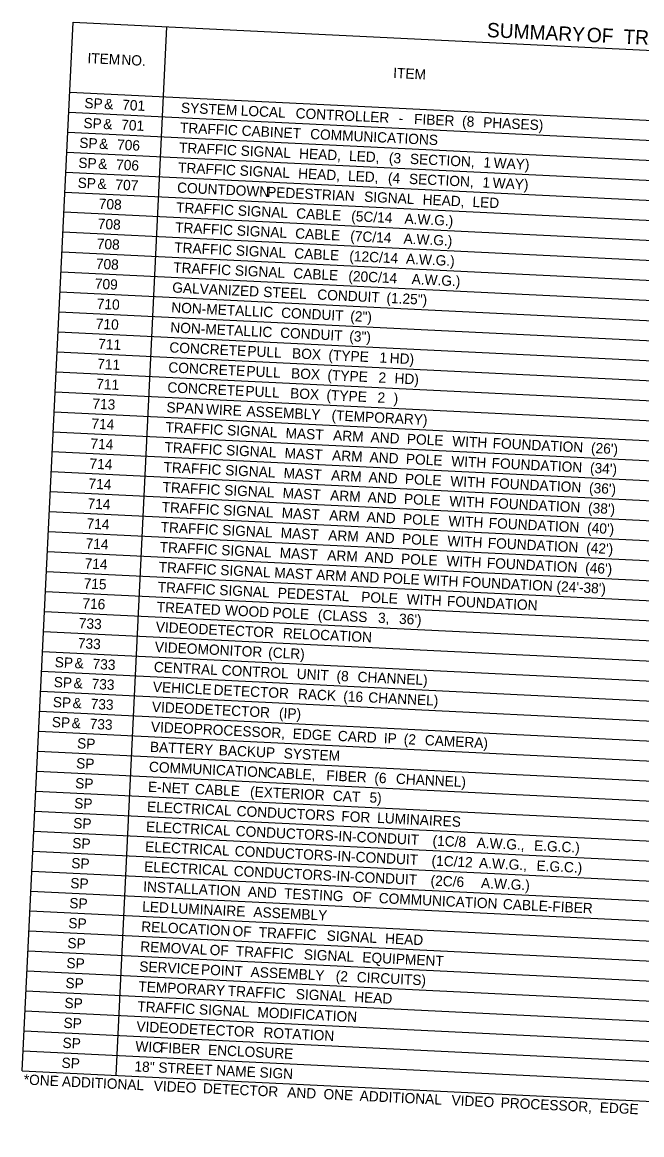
# Model space of a CAD drawing. Extents: x 669100 to 670534, y 743337 to 744379.
# Drawn here: x 670213.3 to 670358.8, y 743747.4 to 744008.6 of the extents above; entities that cross this region are included whole.
import ezdxf

# ---------------------------------------------------------------- set-up
doc = ezdxf.new("R2010")
doc.units = 0
doc.layers.add('R_Dimension', color=7, linetype='Continuous')

msp = doc.modelspace()

# ---------------------------------------------------------------- linework, layer by layer
at = {"layer": 'R_Dimension'}
for p, q in [((670213.29, 743762.42), (670225.24, 744008.56)), ((670225.24, 744008.56), (670534.49, 743993.54)), ((670235.33, 743761.35), (670247.28, 744007.49)), ((670224.45, 743992.15), (670533.69, 743977.13)), ((670224.22, 743987.46), (670533.46, 743972.45)), ((670223.99, 743982.77), (670533.23, 743967.76)), ((670223.76, 743978.09), (670533.01, 743963.07)), ((670223.54, 743973.4), (670532.78, 743958.38)), ((670223.31, 743968.71), (670532.55, 743953.69)), ((670223.08, 743964.02), (670532.32, 743949)), ((670222.85, 743959.33), (670532.09, 743944.32)), ((670222.63, 743954.64), (670531.87, 743939.63)), ((670222.4, 743949.96), (670531.64, 743934.94)), ((670222.17, 743945.27), (670531.41, 743930.25)), ((670221.94, 743940.58), (670531.18, 743925.56)), ((670221.71, 743935.89), (670530.96, 743920.87)), ((670221.49, 743931.2), (670530.73, 743916.19)), ((670221.26, 743926.51), (670530.5, 743911.5)), ((670221.03, 743921.83), (670530.27, 743906.81)), ((670220.8, 743917.14), (670530.05, 743902.12)), ((670220.58, 743912.45), (670529.82, 743897.43)), ((670220.35, 743907.76), (670529.59, 743892.74)), ((670220.12, 743903.07), (670529.36, 743888.05)), ((670219.89, 743898.38), (670529.14, 743883.37)), ((670219.67, 743893.69), (670528.91, 743878.68)), ((670219.44, 743889.01), (670528.68, 743873.99)), ((670219.21, 743884.32), (670528.45, 743869.3)), ((670218.98, 743879.63), (670528.22, 743864.61)), ((670218.76, 743874.94), (670528, 743859.92)), ((670218.53, 743870.25), (670527.77, 743855.24)), ((670218.3, 743865.56), (670527.54, 743850.55)), ((670218.07, 743860.88), (670527.31, 743845.86)), ((670217.84, 743856.19), (670527.09, 743841.17)), ((670217.62, 743851.5), (670526.86, 743836.48)), ((670217.39, 743846.81), (670526.63, 743831.79)), ((670217.16, 743842.12), (670526.4, 743827.11)), ((670216.93, 743837.43), (670526.18, 743822.42)), ((670216.71, 743832.75), (670525.95, 743817.73)), ((670216.48, 743828.06), (670525.72, 743813.04)), ((670216.25, 743823.37), (670525.49, 743808.35)), ((670216.02, 743818.68), (670525.26, 743803.66)), ((670215.8, 743813.99), (670525.04, 743798.98)), ((670215.57, 743809.3), (670524.81, 743794.29)), ((670215.34, 743804.62), (670524.58, 743789.6)), ((670215.11, 743799.93), (670524.35, 743784.91)), ((670214.88, 743795.24), (670524.13, 743780.22)), ((670214.66, 743790.55), (670523.9, 743775.53)), ((670214.43, 743785.86), (670523.67, 743770.85)), ((670214.2, 743781.17), (670523.44, 743766.16)), ((670213.97, 743776.49), (670523.22, 743761.47)), ((670213.75, 743771.8), (670522.99, 743756.78)), ((670213.52, 743767.11), (670522.76, 743752.09)), ((670213.29, 743762.42), (670522.53, 743747.4))]:
    msp.add_line(p, q, dxfattribs=at)

# ---------------------------------------------------------------- texts
for s, height, p in [('SUMMARY', 3.37, (670322.35, 744005.09)), (' OF', 3.37, (670344.56, 744004.02)), (' TRAFFIC', 3.37, (670353.15, 744003.6)), ('ITEM', 2.407, (670228.56, 743998.97)), (' NO.', 2.407, (670235.64, 743998.63)), ('ITEM', 2.407, (670300.36, 743995.48)), ('SP', 2.407, (670227.84, 743988.43)), (' &', 2.407, (670231.61, 743988.25)), (' 701', 2.407, (670235.83, 743988.04)), ('SYSTEM', 2.407, (670250.53, 743987.33)), (' LOCAL', 2.407, (670263.67, 743986.69)), (' CONTROLLER', 2.4071, (670276.56, 743986.07)), ('SP', 2.407, (670227.62, 743983.74)), (' &', 2.407, (670231.38, 743983.56)), (' 701', 2.407, (670235.6, 743983.35)), (' -', 2.407, (670300.79, 743984.89)), (' FIBER', 2.407, (670304.37, 743984.71)), (' (8', 2.407, (670315.65, 743984.17)), (' PHASES)', 2.407, (670320.6, 743983.93)), ('TRAFFIC', 2.407, (670250.3, 743982.64)), (' CABINET', 2.407, (670263.88, 743981.98)), (' COMMUNICATIONS', 2.4071, (670279.97, 743981.2)), ('SP', 2.407, (670226.64, 743979.09)), (' &', 2.407, (670230.41, 743978.91)), (' 706', 2.407, (670234.63, 743978.7)), ('TRAFFIC', 2.407, (670250.07, 743977.95)), (' SIGNAL', 2.407, (670263.65, 743977.29)), (' HEAD,', 2.407, (670277.37, 743976.63)), (' LED,', 2.407, (670289.09, 743976.06)), (' (3', 2.407, (670298.46, 743975.6)), (' SECTION,', 2.407, (670303.4, 743975.36)), ('SP', 2.407, (670226.41, 743974.4)), (' &', 2.407, (670230.18, 743974.22)), (' 706', 2.407, (670234.4, 743974.01)), ('TRAFFIC', 2.407, (670249.85, 743973.26)), (' SIGNAL', 2.407, (670263.42, 743972.61)), (' 1', 2.407, (670320.65, 743974.53)), (' WAY)', 2.407, (670323.06, 743974.41)), (' HEAD,', 2.407, (670277.15, 743971.94)), (' LED,', 2.407, (670288.86, 743971.37)), (' (4', 2.407, (670298.24, 743970.91)), (' SECTION,', 2.407, (670303.18, 743970.67)), ('SP', 2.407, (670226.25, 743969.71)), (' &', 2.407, (670230.02, 743969.53)), (' 707', 2.407, (670234.24, 743969.32)), ('COUNTDOWN', 2.407, (670249.62, 743968.58)), (' PEDESTRIAN', 2.4071, (670269.86, 743967.59)), (' 1', 2.407, (670320.42, 743969.84)), (' WAY)', 2.407, (670322.83, 743969.72)), ('708', 2.407, (670231.22, 743964.77)), (' SIGNAL', 2.407, (670292.65, 743966.49)), (' HEAD,', 2.407, (670306.38, 743965.82)), (' LED', 2.407, (670318.09, 743965.25)), ('TRAFFIC', 2.407, (670249.39, 743963.89)), (' SIGNAL', 2.407, (670262.97, 743963.23)), (' CABLE', 2.407, (670276.69, 743962.56)), ('708', 2.407, (670230.99, 743960.08)), (' (5C/14', 2.407, (670289.62, 743961.93)), (' A.W.G.)', 2.407, (670302.13, 743961.33)), ('TRAFFIC', 2.407, (670249.16, 743959.2)), (' SIGNAL', 2.407, (670262.74, 743958.54)), (' CABLE', 2.407, (670276.46, 743957.87)), (' (7C/14', 2.407, (670289.39, 743957.25)), ('708', 2.407, (670230.76, 743955.39)), ('TRAFFIC', 2.407, (670248.94, 743954.51)), (' A.W.G.)', 2.407, (670301.91, 743956.64)), (' SIGNAL', 2.407, (670262.51, 743953.85)), (' CABLE', 2.407, (670276.24, 743953.19)), (' (12C/14', 2.407, (670289.17, 743952.56)), (' A.W.G.)', 2.407, (670302.47, 743951.91)), ('708', 2.407, (670230.54, 743950.7)), ('TRAFFIC', 2.407, (670248.71, 743949.82)), (' SIGNAL', 2.407, (670262.28, 743949.16)), (' CABLE', 2.407, (670276.01, 743948.5)), (' (20C/14', 2.407, (670288.94, 743947.87)), (' A.W.G.)', 2.407, (670303.8, 743947.15)), ('709', 2.407, (670230.3, 743946.02)), ('GALVANIZED', 2.407, (670248.48, 743945.13)), (' STEEL', 2.407, (670268.95, 743944.14)), ('710', 2.407, (670230.75, 743941.3)), (' CONDUIT', 2.407, (670281.65, 743943.52)), (' (1.25")', 2.407, (670297.89, 743942.73)), ('NON-METALLIC', 2.4071, (670248.25, 743940.45)), (' CONDUIT', 2.407, (670273.15, 743939.24)), (' (2")', 2.407, (670289.39, 743938.45)), ('710', 2.407, (670230.53, 743936.61)), ('NON-METALLIC', 2.4071, (670248.03, 743935.76)), (' CONDUIT', 2.407, (670272.92, 743934.55)), (' (3")', 2.407, (670289.16, 743933.76)), ('711', 2.407, (670231.08, 743931.88)), ('CONCRETE', 2.407, (670247.8, 743931.07)), (' PULL', 2.407, (670265.21, 743930.22)), (' BOX', 2.407, (670275.72, 743929.71)), (' (TYPE', 2.407, (670284.26, 743929.3)), (' 1', 2.407, (670296.24, 743928.72)), (' HD)', 2.407, (670298.65, 743928.6)), ('711', 2.407, (670230.86, 743927.19)), ('CONCRETE', 2.407, (670247.57, 743926.38)), (' PULL', 2.407, (670264.99, 743925.53)), (' BOX', 2.407, (670275.49, 743925.02)), (' (TYPE', 2.407, (670284.03, 743924.61)), (' 2', 2.407, (670296.02, 743924.03)), (' HD)', 2.407, (670299.78, 743923.85)), ('711', 2.407, (670230.63, 743922.5)), ('CONCRETE', 2.407, (670247.34, 743921.69)), (' PULL', 2.407, (670264.76, 743920.85)), (' BOX', 2.407, (670275.27, 743920.34)), ('713', 2.407, (670229.72, 743917.85)), (' (TYPE', 2.407, (670283.8, 743919.92)), (' 2', 2.407, (670295.79, 743919.34)), (' )', 2.407, (670299.56, 743919.16)), ('SPAN', 2.407, (670247.11, 743917)), (' WIRE', 2.407, (670255.5, 743916.6)), (' ASSEMBLY', 2.407, (670265.02, 743916.13)), (' (TEMPORARY)', 2.4071, (670285, 743915.16)), ('714', 2.407, (670229.49, 743913.16)), ('TRAFFIC', 2.407, (670246.89, 743912.32)), (' SIGNAL', 2.407, (670260.46, 743911.66)), (' MAST', 2.407, (670274.19, 743910.99)), (' ARM', 2.407, (670285.36, 743910.45)), (' AND', 2.407, (670294.16, 743910.02)), ('714', 2.407, (670229.26, 743908.47)), ('TRAFFIC', 2.407, (670246.66, 743907.63)), (' POLE', 2.407, (670302.68, 743909.61)), (' WITH', 2.407, (670313.34, 743909.09)), (' FOUNDATION', 2.4071, (670322.82, 743908.63)), (" (26')", 2.407, (670345.92, 743907.51)), (' SIGNAL', 2.407, (670260.23, 743906.97)), (' MAST', 2.407, (670273.96, 743906.3)), (' ARM', 2.407, (670285.13, 743905.76)), (' AND', 2.407, (670293.93, 743905.33)), (' POLE', 2.407, (670302.45, 743904.92)), ('714', 2.407, (670229.04, 743903.78)), ('TRAFFIC', 2.407, (670246.43, 743902.94)), (' SIGNAL', 2.407, (670260.01, 743902.28)), (' WITH', 2.407, (670313.11, 743904.4)), (' FOUNDATION', 2.4071, (670322.59, 743903.94)), (" (34')", 2.407, (670345.69, 743902.82)), (' MAST', 2.407, (670273.73, 743901.61)), (' ARM', 2.407, (670284.9, 743901.07)), (' AND', 2.407, (670293.7, 743900.64)), (' POLE', 2.407, (670302.22, 743900.23)), (' WITH', 2.407, (670312.88, 743899.71)), ('714', 2.407, (670228.81, 743899.09)), ('TRAFFIC', 2.407, (670246.2, 743898.25)), (' SIGNAL', 2.407, (670259.78, 743897.59)), (' MAST', 2.407, (670273.5, 743896.92)), (' FOUNDATION', 2.4071, (670322.37, 743899.25)), (" (36')", 2.407, (670345.46, 743898.13)), ('714', 2.407, (670228.58, 743894.41)), (' ARM', 2.407, (670284.67, 743896.38)), (' AND', 2.407, (670293.48, 743895.95)), (' POLE', 2.407, (670302, 743895.54)), (' WITH', 2.407, (670312.65, 743895.02)), (' FOUNDATION', 2.4071, (670322.14, 743894.56)), ('TRAFFIC', 2.407, (670245.98, 743893.56)), (' SIGNAL', 2.407, (670259.55, 743892.9)), (' MAST', 2.407, (670273.28, 743892.24)), (' ARM', 2.407, (670284.45, 743891.69)), (" (38')", 2.407, (670345.23, 743893.44)), ('714', 2.407, (670228.35, 743889.72)), (' AND', 2.407, (670293.25, 743891.27)), (' POLE', 2.407, (670301.77, 743890.85)), (' WITH', 2.407, (670312.43, 743890.34)), (' FOUNDATION', 2.4071, (670321.91, 743889.87)), ('TRAFFIC', 2.407, (670245.75, 743888.87)), (' SIGNAL', 2.407, (670259.32, 743888.21)), (' MAST', 2.407, (670273.05, 743887.55)), (' ARM', 2.407, (670284.22, 743887.01)), (' AND', 2.407, (670293.02, 743886.58)), (" (40')", 2.407, (670345.01, 743888.75)), ('714', 2.407, (670228.13, 743885.03)), ('TRAFFIC', 2.407, (670245.52, 743884.19)), (' POLE', 2.407, (670301.54, 743886.16)), (' WITH', 2.407, (670312.2, 743885.65)), (' FOUNDATION', 2.4071, (670321.68, 743885.19)), (" (42')", 2.407, (670344.78, 743884.06)), (' SIGNAL', 2.407, (670259.09, 743883.53)), (' MAST', 2.407, (670272.82, 743882.86)), (' ARM', 2.407, (670283.99, 743882.32)), (' AND', 2.407, (670292.79, 743881.89)), (' POLE', 2.407, (670301.31, 743881.48)), ('714', 2.407, (670227.9, 743880.34)), ("TRAFFIC SIGNAL MAST ARM AND POLE WITH FOUNDATION (24'-38')", 2.4071, (670245.29, 743879.5)), (' WITH', 2.407, (670311.97, 743880.96)), (' FOUNDATION', 2.4071, (670321.46, 743880.5)), (" (46')", 2.407, (670344.55, 743879.38)), ('715', 2.407, (670227.67, 743875.65)), ('TRAFFIC', 2.407, (670245.07, 743874.81)), (' SIGNAL', 2.407, (670258.64, 743874.15)), (' PEDESTAL', 2.407, (670272.36, 743873.48)), ('716', 2.407, (670227.38, 743870.97)), (' POLE', 2.407, (670291.96, 743872.53)), (' WITH', 2.407, (670302.62, 743872.01)), (' FOUNDATION', 2.4071, (670312.1, 743871.55)), ('TREATED', 2.407, (670244.84, 743870.12)), (' WOOD', 2.407, (670259.96, 743869.39)), (' POLE', 2.407, (670271.13, 743868.84)), (' (CLASS', 2.407, (670281.79, 743868.33)), ('733', 2.407, (670226.53, 743866.31)), ('VIDEO', 2.407, (670244.61, 743865.43)), (' 3,', 2.407, (670295.9, 743867.64)), (" 36')", 2.407, (670300.84, 743867.4)), (' DETECTOR', 2.407, (670253.75, 743864.99)), (' RELOCATION', 2.4071, (670273.56, 743864.03)), ('733', 2.407, (670226.31, 743861.62)), ('VIDEO', 2.407, (670244.38, 743860.74)), (' MONITOR', 2.407, (670253.53, 743860.3)), (' (CLR)', 2.407, (670270.11, 743859.49)), ('SP', 2.407, (670220.88, 743857.18)), (' &', 2.407, (670224.65, 743857)), (' 733', 2.407, (670228.87, 743856.8)), ('CENTRAL', 2.407, (670244.16, 743856.05)), (' CONTROL', 2.407, (670259.19, 743855.32)), ('SP', 2.407, (670220.65, 743852.5)), (' UNIT', 2.407, (670276.81, 743854.47)), (' (8', 2.407, (670286.16, 743854.01)), (' CHANNEL)', 2.407, (670291.11, 743853.77)), (' &', 2.407, (670224.42, 743852.31)), (' 733', 2.407, (670228.64, 743852.11)), ('VEHICLE', 2.407, (670243.93, 743851.37)), (' DETECTOR', 2.407, (670257.29, 743850.72)), (' RACK', 2.407, (670277.1, 743849.76)), ('SP', 2.407, (670220.43, 743847.81)), (' &', 2.407, (670224.19, 743847.63)), (' 733', 2.407, (670228.42, 743847.42)), (' (16', 2.407, (670287.75, 743849.24)), (' CHANNEL)', 2.407, (670293.62, 743848.95)), ('VIDEO', 2.407, (670243.7, 743846.68)), (' DETECTOR', 2.407, (670252.84, 743846.23)), (' (IP)', 2.407, (670272.65, 743845.27)), ('SP', 2.407, (670220.2, 743843.12)), (' &', 2.407, (670223.97, 743842.94)), (' 733', 2.407, (670228.19, 743842.73)), ('VIDEO', 2.407, (670243.47, 743841.99)), (' PROCESSOR,', 2.4071, (670252.62, 743841.55)), (' EDGE', 2.407, (670275.88, 743840.42)), (' CARD', 2.407, (670286.47, 743839.9)), (' IP', 2.407, (670297.26, 743839.38)), ('SP', 2.407, (670226.12, 743838.13)), ('BATTERY', 2.407, (670243.24, 743837.3)), (' (2', 2.407, (670301.95, 743839.15)), (' CAMERA)', 2.407, (670306.89, 743838.91)), (' BACKUP', 2.407, (670258.5, 743836.56)), (' SYSTEM', 2.407, (670273.76, 743835.82)), ('SP', 2.407, (670225.9, 743833.44)), ('COMMUNICATION', 2.4071, (670243.02, 743832.61)), (' CABLE,', 2.407, (670269.77, 743831.31)), (' FIBER', 2.407, (670283.76, 743830.63)), (' (6', 2.407, (670295.04, 743830.09)), (' CHANNEL)', 2.407, (670300.11, 743829.84)), ('SP', 2.407, (670225.67, 743828.76)), ('E-NET', 2.407, (670242.79, 743827.92)), (' CABLE', 2.407, (670252.92, 743827.43)), (' (EXTERIOR', 2.407, (670265.85, 743826.8)), ('SP', 2.407, (670225.44, 743824.07)), (' CAT', 2.407, (670285.31, 743825.86)), (' 5)', 2.407, (670293.9, 743825.44)), ('ELECTRICAL', 2.407, (670242.56, 743823.24)), (' CONDUCTORS', 2.4071, (670262.7, 743822.26)), (' FOR', 2.407, (670287.3, 743821.06)), ('SP', 2.407, (670225.21, 743819.38)), ('ELECTRICAL', 2.407, (670242.33, 743818.55)), (' LUMINAIRES', 2.4071, (670295.7, 743820.66)), (' CONDUCTORS-IN-CONDUIT', 2.4071, (670262.48, 743817.57)), ('SP', 2.407, (670224.99, 743814.69)), ('ELECTRICAL', 2.407, (670242.11, 743813.86)), (' (1C/8', 2.407, (670308.71, 743815.32)), (' A.W.G.,', 2.407, (670319.06, 743814.82)), (' E.G.C.)', 2.407, (670332.56, 743814.17)), (' CONDUCTORS-IN-CONDUIT', 2.4071, (670262.25, 743812.88)), (' (1C/12', 2.407, (670308.48, 743810.64)), ('SP', 2.407, (670224.76, 743810)), ('ELECTRICAL', 2.407, (670241.88, 743809.17)), (' CONDUCTORS-IN-CONDUIT', 2.4071, (670262.02, 743808.19)), (' A.W.G.,', 2.407, (670319.63, 743810.09)), (' E.G.C.)', 2.407, (670333.13, 743809.44)), ('SP', 2.407, (670224.53, 743805.31)), (' (2C/6', 2.407, (670308.25, 743805.95)), ('INSTALLATION', 2.4071, (670241.65, 743804.48)), (' AND', 2.407, (670265.33, 743803.33)), (' TESTING', 2.407, (670273.85, 743802.92)), (' A.W.G.)', 2.407, (670320.1, 743805.37)), ('SP', 2.407, (670224.3, 743800.63)), (' OF', 2.407, (670289.94, 743802.14)), (' COMMUNICATION', 2.4071, (670296.08, 743801.84)), (' CABLE-FIBER', 2.4071, (670325.23, 743800.42)), ('LED', 2.407, (670241.42, 743799.79)), (' LUMINAIRE', 2.407, (670247.23, 743799.51)), (' ASSEMBLY', 2.407, (670266.64, 743798.57)), ('SP', 2.407, (670224.07, 743795.94)), ('RELOCATION', 2.407, (670241.2, 743795.11)), (' OF', 2.407, (670261.74, 743794.11)), (' TRAFFIC', 2.407, (670267.87, 743793.81)), (' SIGNAL', 2.407, (670283.85, 743793.03)), (' HEAD', 2.407, (670297.57, 743792.37)), ('SP', 2.407, (670223.85, 743791.25)), ('REMOVAL', 2.407, (670240.97, 743790.42)), (' OF', 2.407, (670256.38, 743789.67)), (' TRAFFIC', 2.407, (670262.51, 743789.37)), (' SIGNAL', 2.407, (670278.49, 743788.6)), (' EQUIPMENT', 2.407, (670292.22, 743787.93)), ('SP', 2.407, (670223.62, 743786.56)), ('SERVICE', 2.407, (670240.74, 743785.73)), (' POINT', 2.407, (670254.33, 743785.07)), (' ASSEMBLY', 2.407, (670265.99, 743784.5)), ('SP', 2.407, (670223.39, 743781.87)), (' (2', 2.407, (670285.97, 743783.53)), (' CIRCUITS)', 2.407, (670290.91, 743783.29)), ('TEMPORARY', 2.407, (670240.51, 743781.04)), (' TRAFFIC', 2.407, (670260.62, 743780.06)), (' SIGNAL', 2.407, (670276.6, 743779.29)), ('SP', 2.407, (670223.16, 743777.18)), (' HEAD', 2.407, (670290.32, 743778.62)), ('TRAFFIC', 2.407, (670240.28, 743776.35)), (' SIGNAL', 2.407, (670253.86, 743775.69)), (' MODIFICATION', 2.4071, (670267.58, 743775.03)), ('SP', 2.407, (670222.94, 743772.5)), ('VIDEO', 2.407, (670240.06, 743771.66)), (' DETECTOR', 2.407, (670249.2, 743771.22)), (' ROTATION', 2.407, (670269, 743770.26)), ('SP', 2.407, (670222.71, 743767.81)), ('WIC', 2.407, (670239.83, 743766.98)), (' FIBER', 2.407, (670244.69, 743766.74)), (' ENCLOSURE', 2.407, (670255.98, 743766.19)), ('SP', 2.407, (670222.48, 743763.12)), ('18" STREET NAME SIGN', 2.4071, (670239.6, 743762.29)), ('*ONE', 2.407, (670213.61, 743759.2)), (' ADDITIONAL', 2.4071, (670221.67, 743758.81)), (' VIDEO', 2.407, (670243.23, 743757.76)), (' DETECTOR', 2.407, (670254.78, 743757.2)), (' AND', 2.407, (670274.58, 743756.24)), (' ONE', 2.407, (670283.1, 743755.83)), (' ADDITIONAL', 2.4071, (670291.6, 743755.42)), (' VIDEO', 2.407, (670313.17, 743754.37)), (' PROCESSOR,', 2.4071, (670324.71, 743753.81)), (' EDGE', 2.407, (670347.98, 743752.68))]:
    msp.add_text(s, height=height, rotation=357.2199, dxfattribs=at).set_placement(p)

doc.saveas('drawing.dxf')
